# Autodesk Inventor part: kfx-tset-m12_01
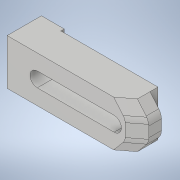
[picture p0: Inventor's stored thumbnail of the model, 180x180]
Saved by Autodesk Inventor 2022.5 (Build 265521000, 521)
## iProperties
Created: 2021-10
Part Number: kfx-tset-m12_01
Material: 一般
Document SubType Name: Modeling
Designer: ImaoCorp
Density: 1 g/cm^3
Appearance: 既定
Author: ImaoCorp
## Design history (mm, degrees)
feature "kfx-tset-m12_01"
node "ソリッド1"
